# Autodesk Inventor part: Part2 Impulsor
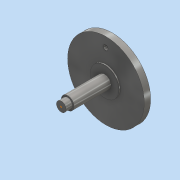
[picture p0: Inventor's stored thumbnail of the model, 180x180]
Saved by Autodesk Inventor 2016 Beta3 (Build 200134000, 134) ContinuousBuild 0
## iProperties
Created: 2015-11
Part Number: Part2 Impulsor
Material: Aluminum 6061-AHC
Document SubType Name: Modeling
Designer: SanPer86
Density: 2.7 g/cm^3
Appearance: Aluminum - Dark
Mass: 0.0525588 g
Surface Area: 0.817918 cm^2
Volume: 0.0194662 cm^3
Author: SanPer86
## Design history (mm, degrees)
sketch "Sketch1"
  geometry: L1 (0, 0)-(0, 4.5); L2 (-1.485, 4)-(-3, 4); L3 (-3, 4)-(-3, 3.5); L4 (-3, 3.5)-(-1.125, 3.5); L5 (-0.5, 3.4)-(-0.5, 0.5); L6 (-0.5, 0.5)-(-0.375, 0.5); L7 (-0.375, 0.5)-(-0.375, 0); L8 (-0.375, 0)-(0, 0); L9 (-0.5, 3.4)-(-1.125, 3.4); L10 (-1.125, 3.4)-(-1.125, 3.5); L11 (-1.485, 4)-(-1.485, 4.5); L12 (-1.485, 4.5)-(0, 4.5)
  constraints: 24 end point, 6 perpendicular, 2 horizontal, 2 vertical, 1 parallel
  dimensions: "d6" = 6 diameter of L2.end L1; "d17" = 0.75 diameter of L7.end L1; "d18" = 0.5 vertical distance of L7.end L5.end; "d22" = 0.1 distance of L9.end L4.end; "d24" = 0.5 distance of L3.end L2.end; "d25" = 1 diameter of L5 L1; "d26" = 4.5 distance of L1.start L1.end; "d39" = 0.5 vertical distance of L2.end L11.end; "d44" = 2.97 diameter of L11.end L1; "d45" = 2.25 diameter of L10 L1
revolve "Revolution1" sketch "Sketch1" stored, may be unused: angle "d27" = 90 deg
sketch "Sketch2" dims "d28" = 4.5
  geometry: C1 r 3 at (0, 0) reference; C2 r 0.188 at (-0.017, -2.25); 2 further points
  constraints: 1 centre point, 1 coincident, 3 other
  dimensions: "d29" = 0.375 diameter of C2
extrude "Extrusion1" cut sketch "Sketch2" distance "d30" = 0.5; taper "d31" = 0 deg
sketch "Sketch6"
  geometry: C1 r 2.6 at (-0.009, -3); 2 further points
  constraints: 1 centre point, 2 other
  dimensions: "d41" = 5.2 diameter of C1
extrude "Extrusion3" cut sketch "Sketch6" distance "d42" = 0.5; taper "d43" = 0 deg
body "Solid1"
